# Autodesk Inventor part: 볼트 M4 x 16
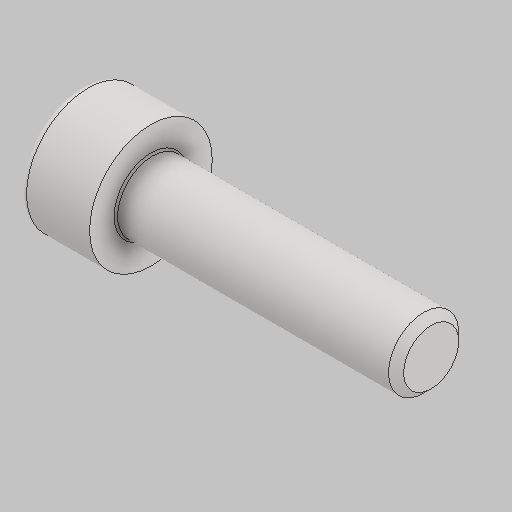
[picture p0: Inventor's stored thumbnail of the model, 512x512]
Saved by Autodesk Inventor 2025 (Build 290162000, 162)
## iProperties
Created: 2024-07
Part Number: 볼트 M4 x 16
Material: 스테인리스강
Description: 6각 소켓 머리 캡 나사
Document SubType Name: Modeling
Designer: 현기
Density: 8.08 g/cm^3
Appearance: 기본값
Author: jhkim
Sending System: Autodesk Inventor 2025
Preprocessor: ST-DEVELOPER v20
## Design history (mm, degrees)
feature "Solid1"
node "솔리드1"
